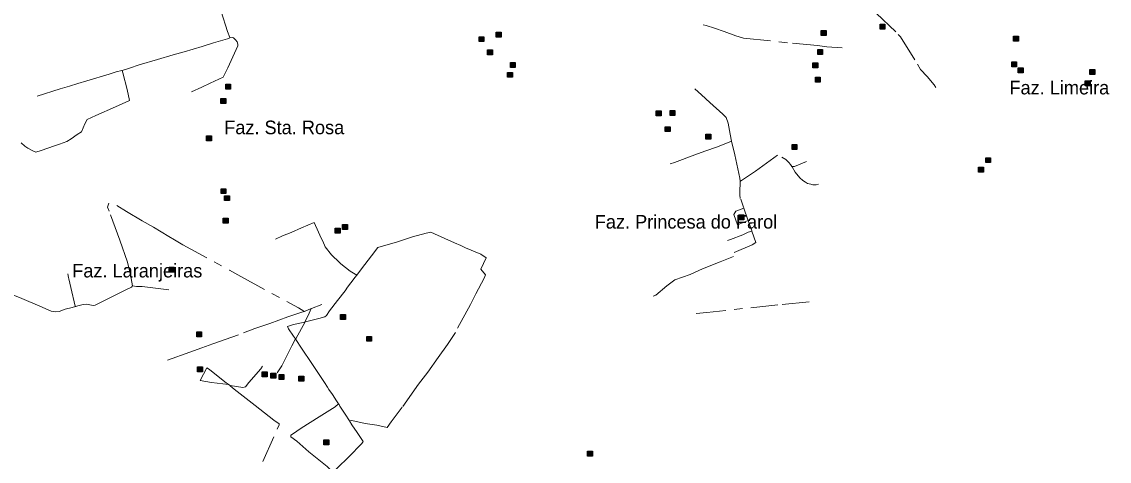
# Model space of a CAD drawing. Extents: x 393.5 to 446.9, y 8064.8 to 8120.4.
# Drawn here: x 404.99 to 417.81, y 8098.67 to 8103.85 of the extents above; entities that cross this region are included whole.
import ezdxf

# ---------------------------------------------------------------- set-up
doc = ezdxf.new("R2010")
doc.units = 0
doc.header["$LTSCALE"] = 0.064
doc.linetypes.add('DOT_DASHED', pattern=[7.7, 5, -1.2, 0.3, -1.2])
doc.layers.add('2', color=7, linetype='Continuous', lineweight=25)
doc.layers.add('22', color=7, linetype='DOT_DASHED', lineweight=13)
doc.layers.add('61', color=7, linetype='Continuous')

msp = doc.modelspace()

# ---------------------------------------------------------------- hatches: boundary and pattern name
at = {"layer": '2'}
for points in [[(410.5847, 8103.7231), (410.6427, 8103.7231), (410.6427, 8103.6651), (410.5847, 8103.6651)], [(414.4164, 8103.7429), (414.4744, 8103.7429), (414.4744, 8103.6849), (414.4164, 8103.6849)], [(415.1109, 8103.8183), (415.1689, 8103.8183), (415.1689, 8103.7603), (415.1109, 8103.7603)], [(410.3818, 8103.671), (410.4398, 8103.671), (410.4398, 8103.613), (410.3818, 8103.613)], [(416.6857, 8103.6772), (416.7437, 8103.6772), (416.7437, 8103.6192), (416.6857, 8103.6192)], [(410.4811, 8103.5164), (410.5391, 8103.5164), (410.5391, 8103.4584), (410.4811, 8103.4584)], [(414.3755, 8103.5188), (414.4335, 8103.5188), (414.4335, 8103.4608), (414.3755, 8103.4608)], [(410.7513, 8103.3666), (410.8093, 8103.3666), (410.8093, 8103.3086), (410.7513, 8103.3086)], [(414.3178, 8103.3643), (414.3758, 8103.3643), (414.3758, 8103.3063), (414.3178, 8103.3063)], [(416.6644, 8103.3751), (416.7224, 8103.3751), (416.7224, 8103.3171), (416.6644, 8103.3171)], [(410.7179, 8103.2515), (410.7759, 8103.2515), (410.7759, 8103.1935), (410.7179, 8103.1935)], [(416.7416, 8103.3051), (416.7996, 8103.3051), (416.7996, 8103.2471), (416.7416, 8103.2471)], [(417.5864, 8103.2845), (417.6444, 8103.2845), (417.6444, 8103.2265), (417.5864, 8103.2265)], [(407.3939, 8103.1126), (407.4519, 8103.1126), (407.4519, 8103.0546), (407.3939, 8103.0546)], [(414.3482, 8103.1939), (414.4062, 8103.1939), (414.4062, 8103.1359), (414.3482, 8103.1359)], [(417.531, 8103.1516), (417.589, 8103.1516), (417.589, 8103.0936), (417.531, 8103.0936)], [(407.3377, 8102.9444), (407.3957, 8102.9444), (407.3957, 8102.8864), (407.3377, 8102.8864)], [(412.4703, 8102.7977), (412.5283, 8102.7977), (412.5283, 8102.7397), (412.4703, 8102.7397)], [(412.6346, 8102.8011), (412.6926, 8102.8011), (412.6926, 8102.7431), (412.6346, 8102.7431)], [(412.5788, 8102.6115), (412.6368, 8102.6115), (412.6368, 8102.5535), (412.5788, 8102.5535)], [(407.1671, 8102.5016), (407.2251, 8102.5016), (407.2251, 8102.4436), (407.1671, 8102.4436)], [(413.0577, 8102.5237), (413.1157, 8102.5237), (413.1157, 8102.4657), (413.0577, 8102.4657)], [(414.0737, 8102.4006), (414.1317, 8102.4006), (414.1317, 8102.3426), (414.0737, 8102.3426)], [(416.3576, 8102.2459), (416.4156, 8102.2459), (416.4156, 8102.1879), (416.3576, 8102.1879)], [(416.2741, 8102.1336), (416.3321, 8102.1336), (416.3321, 8102.0756), (416.2741, 8102.0756)], [(407.3386, 8101.8811), (407.3966, 8101.8811), (407.3966, 8101.8231), (407.3386, 8101.8231)], [(407.3793, 8101.7981), (407.4373, 8101.7981), (407.4373, 8101.7401), (407.3793, 8101.7401)], [(407.3638, 8101.5318), (407.4218, 8101.5318), (407.4218, 8101.4738), (407.3638, 8101.4738)], [(413.4461, 8101.5727), (413.5041, 8101.5727), (413.5041, 8101.5147), (413.4461, 8101.5147)], [(408.6848, 8101.4141), (408.7428, 8101.4141), (408.7428, 8101.3561), (408.6848, 8101.3561)], [(408.7703, 8101.4577), (408.8283, 8101.4577), (408.8283, 8101.3997), (408.7703, 8101.3997)], [(406.7268, 8100.9571), (406.7848, 8100.9571), (406.7848, 8100.8991), (406.7268, 8100.8991)], [(408.7489, 8100.3991), (408.8069, 8100.3991), (408.8069, 8100.3411), (408.7489, 8100.3411)], [(407.0521, 8100.1927), (407.1101, 8100.1927), (407.1101, 8100.1347), (407.0521, 8100.1347)], [(409.0572, 8100.1413), (409.1152, 8100.1413), (409.1152, 8100.0833), (409.0572, 8100.0833)], [(407.0616, 8099.7829), (407.1196, 8099.7829), (407.1196, 8099.7249), (407.0616, 8099.7249)], [(407.8236, 8099.7215), (407.8816, 8099.7215), (407.8816, 8099.6635), (407.8236, 8099.6635)], [(407.9268, 8099.7071), (407.9848, 8099.7071), (407.9848, 8099.6491), (407.9268, 8099.6491)], [(408.0226, 8099.6907), (408.0806, 8099.6907), (408.0806, 8099.6327), (408.0226, 8099.6327)], [(408.2582, 8099.6719), (408.3162, 8099.6719), (408.3162, 8099.6139), (408.2582, 8099.6139)], [(408.5527, 8098.9204), (408.6107, 8098.9204), (408.6107, 8098.8624), (408.5527, 8098.8624)], [(411.6628, 8098.7897), (411.7208, 8098.7897), (411.7208, 8098.7317), (411.6628, 8098.7317)]]:
    msp.add_hatch(color=256, dxfattribs=at).paths.add_polyline_path(points)

# ---------------------------------------------------------------- linework, layer by layer
for points in [[(410.5847, 8103.7231), (410.6427, 8103.7231), (410.6427, 8103.6651), (410.5847, 8103.6651)], [(414.4164, 8103.7429), (414.4744, 8103.7429), (414.4744, 8103.6849), (414.4164, 8103.6849)], [(415.1109, 8103.8183), (415.1689, 8103.8183), (415.1689, 8103.7603), (415.1109, 8103.7603)], [(410.3818, 8103.671), (410.4398, 8103.671), (410.4398, 8103.613), (410.3818, 8103.613)], [(416.6857, 8103.6772), (416.7437, 8103.6772), (416.7437, 8103.6192), (416.6857, 8103.6192)], [(410.4811, 8103.5164), (410.5391, 8103.5164), (410.5391, 8103.4584), (410.4811, 8103.4584)], [(414.3755, 8103.5188), (414.4335, 8103.5188), (414.4335, 8103.4608), (414.3755, 8103.4608)], [(410.7513, 8103.3666), (410.8093, 8103.3666), (410.8093, 8103.3086), (410.7513, 8103.3086)], [(414.3178, 8103.3643), (414.3758, 8103.3643), (414.3758, 8103.3063), (414.3178, 8103.3063)], [(416.6644, 8103.3751), (416.7224, 8103.3751), (416.7224, 8103.3171), (416.6644, 8103.3171)], [(410.7179, 8103.2515), (410.7759, 8103.2515), (410.7759, 8103.1935), (410.7179, 8103.1935)], [(416.7416, 8103.3051), (416.7996, 8103.3051), (416.7996, 8103.2471), (416.7416, 8103.2471)], [(417.5864, 8103.2845), (417.6444, 8103.2845), (417.6444, 8103.2265), (417.5864, 8103.2265)], [(407.3939, 8103.1126), (407.4519, 8103.1126), (407.4519, 8103.0546), (407.3939, 8103.0546)], [(414.3482, 8103.1939), (414.4062, 8103.1939), (414.4062, 8103.1359), (414.3482, 8103.1359)], [(417.531, 8103.1516), (417.589, 8103.1516), (417.589, 8103.0936), (417.531, 8103.0936)], [(407.3377, 8102.9444), (407.3957, 8102.9444), (407.3957, 8102.8864), (407.3377, 8102.8864)], [(412.4703, 8102.7977), (412.5283, 8102.7977), (412.5283, 8102.7397), (412.4703, 8102.7397)], [(412.6346, 8102.8011), (412.6926, 8102.8011), (412.6926, 8102.7431), (412.6346, 8102.7431)], [(412.5788, 8102.6115), (412.6368, 8102.6115), (412.6368, 8102.5535), (412.5788, 8102.5535)], [(407.1671, 8102.5016), (407.2251, 8102.5016), (407.2251, 8102.4436), (407.1671, 8102.4436)], [(413.0577, 8102.5237), (413.1157, 8102.5237), (413.1157, 8102.4657), (413.0577, 8102.4657)], [(414.0737, 8102.4006), (414.1317, 8102.4006), (414.1317, 8102.3426), (414.0737, 8102.3426)], [(416.3576, 8102.2459), (416.4156, 8102.2459), (416.4156, 8102.1879), (416.3576, 8102.1879)], [(416.2741, 8102.1336), (416.3321, 8102.1336), (416.3321, 8102.0756), (416.2741, 8102.0756)], [(407.3386, 8101.8811), (407.3966, 8101.8811), (407.3966, 8101.8231), (407.3386, 8101.8231)], [(407.3793, 8101.7981), (407.4373, 8101.7981), (407.4373, 8101.7401), (407.3793, 8101.7401)], [(407.3638, 8101.5318), (407.4218, 8101.5318), (407.4218, 8101.4738), (407.3638, 8101.4738)], [(413.4461, 8101.5727), (413.5041, 8101.5727), (413.5041, 8101.5147), (413.4461, 8101.5147)], [(408.6848, 8101.4141), (408.7428, 8101.4141), (408.7428, 8101.3561), (408.6848, 8101.3561)], [(408.7703, 8101.4577), (408.8283, 8101.4577), (408.8283, 8101.3997), (408.7703, 8101.3997)], [(406.7268, 8100.9571), (406.7848, 8100.9571), (406.7848, 8100.8991), (406.7268, 8100.8991)], [(408.7489, 8100.3991), (408.8069, 8100.3991), (408.8069, 8100.3411), (408.7489, 8100.3411)], [(407.0521, 8100.1927), (407.1101, 8100.1927), (407.1101, 8100.1347), (407.0521, 8100.1347)], [(409.0572, 8100.1413), (409.1152, 8100.1413), (409.1152, 8100.0833), (409.0572, 8100.0833)], [(407.0616, 8099.7829), (407.1196, 8099.7829), (407.1196, 8099.7249), (407.0616, 8099.7249)], [(407.8236, 8099.7215), (407.8816, 8099.7215), (407.8816, 8099.6635), (407.8236, 8099.6635)], [(407.9268, 8099.7071), (407.9848, 8099.7071), (407.9848, 8099.6491), (407.9268, 8099.6491)], [(408.0226, 8099.6907), (408.0806, 8099.6907), (408.0806, 8099.6327), (408.0226, 8099.6327)], [(408.2582, 8099.6719), (408.3162, 8099.6719), (408.3162, 8099.6139), (408.2582, 8099.6139)], [(408.5527, 8098.9204), (408.6107, 8098.9204), (408.6107, 8098.8624), (408.5527, 8098.8624)], [(411.6628, 8098.7897), (411.7208, 8098.7897), (411.7208, 8098.7317), (411.6628, 8098.7317)]]:
    msp.add_lwpolyline(points, close=True, dxfattribs=at)
at = {"layer": '22'}
for p, q in [((413.3599, 8102.4406), (413.36, 8102.44)), ((408.9396, 8100.8634), (408.9971, 8100.9373)), ((405.6217, 8100.4929), (405.6247, 8100.4936)), ((408.33, 8100.3104), (408.2206, 8100.1119)), ((408.33, 8100.3104), (408.3271, 8100.3097)), ((407.4279, 8099.5729), (407.427, 8099.573)), ((407.4279, 8099.5729), (407.4445, 8099.563)), ((408.7258, 8099.347), (408.7302, 8099.3388))]:
    msp.add_line(p, q, dxfattribs=at)
for points in [[(407.1918, 8104.3959), (407.2696, 8104.1762), (407.3385, 8103.9687), (407.4147, 8103.7322), (407.4411, 8103.6611), (407.4425, 8103.6572)], [(415.0662, 8103.9499), (415.3252, 8103.698), (415.353, 8103.6717), (415.5549, 8103.3486), (415.5874, 8103.2868), (415.6671, 8103.2017), (415.7506, 8103.1028), (415.7692, 8103.0734)], [(413.0246, 8103.8108), (413.0601, 8103.8046), (413.1588, 8103.7707), (413.2744, 8103.7307), (413.4117, 8103.6798), (413.5011, 8103.6552), (414.0798, 8103.5938), (414.3728, 8103.566), (414.4853, 8103.5537), (414.6634, 8103.5384)], [(406.7734, 8103.4564), (406.9023, 8103.4949), (407.1147, 8103.5574), (407.2506, 8103.6), (407.4164, 8103.6479), (407.4425, 8103.6572)], [(406.9899, 8103.0234), (407.1107, 8103.0768), (407.2107, 8103.1247), (407.3625, 8103.1953), (407.4172, 8103.3057), (407.5373, 8103.5632), (407.5386, 8103.5845), (407.5306, 8103.6111), (407.5106, 8103.6364), (407.4853, 8103.6577), (407.4693, 8103.6617), (407.4425, 8103.6572)], [(406.1714, 8103.2746), (406.2607, 8103.3021), (406.3734, 8103.3386), (406.5898, 8103.4023), (406.7734, 8103.4564)], [(404.981, 8102.4212), (405.025, 8102.3826), (405.0596, 8102.3573), (405.1276, 8102.3214), (405.1542, 8102.3107), (405.2182, 8102.332), (405.3761, 8102.3852), (405.4347, 8102.4039), (405.5213, 8102.4385), (405.5706, 8102.4678), (405.6412, 8102.5197), (405.6919, 8102.5503), (405.7332, 8102.6449), (405.7598, 8102.6941), (405.8637, 8102.7434), (406.0942, 8102.8446), (406.26, 8102.9205), (406.2334, 8103.0509), (406.1807, 8103.2453), (406.1724, 8103.2714), (406.1718, 8103.2733), (406.1714, 8103.2746)], [(405.1693, 8102.9724), (405.4411, 8103.0589), (405.5503, 8103.0882), (405.6516, 8103.1215), (405.7542, 8103.1521), (406.018, 8103.2319), (406.102, 8103.2559), (406.1697, 8103.2742), (406.1714, 8103.2746)], [(413.3599, 8102.4406), (413.3431, 8102.5237), (413.3198, 8102.6523), (413.2979, 8102.7207), (413.2554, 8102.759), (413.1035, 8102.8958), (413.0051, 8102.9866), (412.9257, 8103.0563)], [(413.3599, 8102.4406), (413.1932, 8102.3753), (413.0439, 8102.3219)], [(413.36, 8102.44), (413.398, 8102.279), (413.4569, 8102.0031), (413.461, 8101.969), (413.4616, 8101.9639)], [(413.0439, 8102.3219), (412.9269, 8102.2795), (412.6886, 8102.1892), (412.6352, 8102.1728)], [(413.4668, 8101.9685), (413.6419, 8102.0891), (413.9206, 8102.2884)], [(413.951, 8102.2517), (414.0001, 8102.2231), (414.0359, 8102.1896), (414.0564, 8102.1659), (414.0722, 8102.1407)], [(414.0722, 8102.1407), (414.1021, 8102.1439), (414.244, 8102.2006)], [(414.0722, 8102.1407), (414.0733, 8102.1389), (414.0746, 8102.1368)], [(414.0746, 8102.1368), (414.1116, 8102.0746), (414.1652, 8102.0079), (414.201, 8101.9792), (414.2316, 8101.9558), (414.2548, 8101.9433), (414.2961, 8101.9325), (414.3193, 8101.9271), (414.357, 8101.9271), (414.3859, 8101.9328)], [(413.4616, 8101.9639), (413.4593, 8101.8348), (413.4593, 8101.8071), (413.4616, 8101.7656)], [(406.2953, 8100.7376), (406.2702, 8100.8643), (406.2353, 8101.0163), (406.1437, 8101.2739), (406.0192, 8101.6146), (405.9981, 8101.6637), (406.015, 8101.7114)], [(406.1115, 8101.6811), (406.2218, 8101.6109), (406.4086, 8101.5028), (406.542, 8101.427), (406.7246, 8101.319), (406.7907, 8101.2783), (406.8891, 8101.2199), (407.4384, 8100.9197), (407.5704, 8100.8467), (408.253, 8100.4756), (408.3151, 8100.4381), (408.3204, 8100.4349), (408.322, 8100.4355), (408.4033, 8100.4686)], [(413.4687, 8101.7575), (413.5012, 8101.6646), (413.5039, 8101.6568), (413.5051, 8101.6533), (413.5058, 8101.6514)], [(413.5568, 8101.5052), (413.43, 8101.4566), (413.3878, 8101.575), (413.4086, 8101.6165), (413.5051, 8101.6533)], [(413.5058, 8101.6514), (413.5533, 8101.5155), (413.5568, 8101.5052)], [(408.5214, 8101.2965), (408.4892, 8101.3683), (408.4365, 8101.4828), (408.2876, 8101.4196), (408.164, 8101.3649), (408.0629, 8101.3242), (407.9814, 8101.2863)], [(413.5568, 8101.5052), (413.598, 8101.384), (413.5992, 8101.3806)], [(408.6863, 8101.0592), (408.6416, 8101.103), (408.5679, 8101.197), (408.5384, 8101.2629), (408.5214, 8101.2965)], [(408.9971, 8100.9373), (409.1143, 8101.0889), (409.1874, 8101.19), (409.4198, 8101.256), (409.5975, 8101.3122), (409.7576, 8101.3557), (409.8138, 8101.3683), (409.9774, 8101.294), (410.0926, 8101.2449), (410.167, 8101.2112), (410.2218, 8101.1845), (410.4044, 8101.1088), (410.4676, 8101.068), (410.4022, 8100.9346), (410.457, 8100.8673), (410.4409, 8100.8266), (410.344, 8100.6428), (410.2808, 8100.5178), (410.1022, 8100.1853), (410.0115, 8100.0436), (409.8999, 8099.8934), (409.777, 8099.7179), (409.6689, 8099.5761), (409.4744, 8099.3066), (409.3445, 8099.1339), (409.2981, 8099.0694), (409.1774, 8099.0932), (409.0369, 8099.1157), (408.915, 8099.1429), (408.8765, 8099.1499), (408.858, 8099.1474), (408.8535, 8099.1468)], [(413.3139, 8101.2705), (413.349, 8101.2813), (413.4921, 8101.3379), (413.5542, 8101.3703), (413.5992, 8101.3806)], [(413.5992, 8101.3806), (413.646, 8101.2462), (413.6028, 8101.2192), (413.3895, 8101.1302)], [(408.9396, 8100.8634), (408.8607, 8100.9108), (408.7507, 8100.9972), (408.7099, 8101.0393), (408.6917, 8101.0534), (408.6863, 8101.0592)], [(412.5965, 8100.7378), (412.691, 8100.8052), (412.8719, 8100.87), (413.0176, 8100.9374), (413.2255, 8101.0183), (413.382, 8101.0804)], [(405.6195, 8100.4954), (405.6193, 8100.4961), (405.5671, 8100.7157), (405.5447, 8100.8195), (405.5402, 8100.8338), (405.5309, 8100.8791)], [(408.8172, 8100.7022), (408.8202, 8100.7062), (408.9199, 8100.8367), (408.9396, 8100.8634)], [(404.7393, 8100.69), (404.9904, 8100.5891), (405.2017, 8100.4986), (405.3352, 8100.4383), (405.3828, 8100.4319), (405.4305, 8100.4351), (405.4988, 8100.4605), (405.5814, 8100.4811), (405.6217, 8100.4929)], [(406.0112, 8100.5875), (406.1303, 8100.6478), (406.2256, 8100.6938), (406.2826, 8100.7216), (406.2953, 8100.7376)], [(406.7213, 8100.6907), (406.4083, 8100.7272), (406.3432, 8100.7303), (406.2959, 8100.7375), (406.2953, 8100.7376)], [(408.33, 8100.3104), (408.3523, 8100.3179), (408.4913, 8100.3516), (408.563, 8100.3698), (408.584, 8100.3867), (408.6163, 8100.4414), (408.7132, 8100.5635), (408.8017, 8100.6772), (408.8172, 8100.7022)], [(412.4345, 8100.6164), (412.4669, 8100.6272), (412.5965, 8100.7378)], [(405.6247, 8100.4936), (405.6512, 8100.4999), (405.7127, 8100.515), (405.7549, 8100.5192), (405.8096, 8100.5094), (405.8335, 8100.5051), (405.8532, 8100.5094), (405.8925, 8100.529), (405.9265, 8100.5451), (406.0112, 8100.5875)], [(408.4033, 8100.4686), (408.4044, 8100.469), (408.5269, 8100.5149)], [(414.2742, 8100.5469), (413.9071, 8100.5118), (413.0676, 8100.4228), (412.9407, 8100.412)], [(406.7082, 8099.8626), (406.9694, 8099.9552), (407.1113, 8100.0071), (407.2419, 8100.052), (407.6037, 8100.1812), (407.7385, 8100.2331), (407.9135, 8100.2935), (408.127, 8100.3693), (408.278, 8100.4227), (408.3204, 8100.4349)], [(408.4033, 8100.4686), (408.378, 8100.4139), (408.3323, 8100.3153), (408.33, 8100.3104)], [(408.3271, 8100.3097), (408.1937, 8100.2795), (408.1221, 8100.2585), (408.1361, 8100.2304), (408.1951, 8100.1448), (408.2178, 8100.1111)], [(407.999, 8099.7119), (408.0549, 8099.7922), (408.1038, 8099.8883), (408.1755, 8100.0297), (408.2178, 8100.1111), (408.2182, 8100.1118)], [(408.565, 8099.5863), (408.4112, 8099.8202), (408.2881, 8100.0018), (408.2219, 8100.106), (408.2195, 8100.1097), (408.2182, 8100.1118)], [(407.427, 8099.573), (407.2253, 8099.5995), (407.0924, 8099.6211), (407.1721, 8099.7704), (407.2037, 8099.7522), (407.3847, 8099.6045), (407.4279, 8099.5729)], [(407.4445, 8099.563), (407.5964, 8099.5382), (407.6263, 8099.5448), (407.6679, 8099.5996), (407.8074, 8099.7605), (407.8273, 8099.7888)], [(407.83, 8098.6664), (408.0233, 8099.0981), (408.0233, 8099.1098), (407.9602, 8099.1529), (407.7401, 8099.3272), (407.4951, 8099.5181), (407.4476, 8099.5602), (407.4457, 8099.5619), (407.4445, 8099.563)], [(408.594, 8099.5428), (408.586, 8099.5548), (408.565, 8099.5863)], [(408.7258, 8099.347), (408.7001, 8099.3818), (408.6529, 8099.4569), (408.6109, 8099.5163), (408.594, 8099.5428)], [(408.7258, 8099.347), (408.6856, 8099.3121), (408.4969, 8099.1933), (408.2819, 8099.0588), (408.1823, 8098.989), (408.1631, 8098.9768), (408.1631, 8098.9576), (408.233, 8098.9052), (408.3728, 8098.7812), (408.5912, 8098.6066), (408.6367, 8098.5629), (408.6563, 8098.5415)], [(408.7302, 8099.3388), (408.7398, 8099.3208), (408.8027, 8099.2248), (408.8535, 8099.1468)], [(408.8535, 8099.1468), (408.8833, 8099.0981), (408.9462, 8099.0073), (409.0143, 8098.9025), (409.0004, 8098.878), (408.8448, 8098.7209), (408.7103, 8098.5882), (408.6808, 8098.5624), (408.6569, 8098.542), (408.6563, 8098.5415)]]:
    msp.add_lwpolyline(points, dxfattribs=at)

# ---------------------------------------------------------------- texts
at = {"layer": '61'}
for s, p in [('Faz. Limeira', (416.6374, 8102.9915)), ('Faz. Sta. Rosa', (407.3763, 8102.5228)), ('Faz. Princesa do Farol', (411.7467, 8101.4109)), ('Faz. Laranjeiras', (405.5839, 8100.8352))]:
    msp.add_text(s, height=0.16, dxfattribs=at).set_placement(p)

doc.saveas('drawing.dxf')
